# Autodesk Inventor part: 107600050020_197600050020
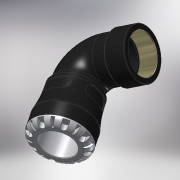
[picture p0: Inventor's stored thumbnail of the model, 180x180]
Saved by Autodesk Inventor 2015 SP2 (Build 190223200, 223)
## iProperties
Created: 2016-12
Part Number: 107600050020_197600050020
Material: PVC-Piping
Description: PLASSON 90° ELBOW WITH FEMALE INTEGRAL BRASS 50X2" SERIES 1
Document SubType Name: Modeling
Designer: KIM
Mass: 664.223 g
Surface Area: 733.008 cm^2
Volume: 474.445 cm^3
Density: 1.4 g/cm^3
Appearance: Black Cast
Author: KIM
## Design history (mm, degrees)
derived "1076.ipt"
feature "Solid1::1076.ipt"
tag "TaggingFeature1"
body "Solid1"
other parameters: "d1" = 33.18, "d3" = 62.5, "d4" = 85, "d8" = 74.8, "d13" = 9, "d14" = 9, "d15" = 0, "d17" = 360 deg, "d19" = 8 deg, "d20" = 1, "d21" = 1, "d22" = 8 deg, "d24" = 0, "d26" = 360 deg, "d33" = 8.5, "d51" = 0.85, "d54" = 17.5, "d55" = 11, "d57" = 17.64, "d58" = 0, "d74" = 0, "d78" = 79, "d82" = 1, "d115" = 360 deg, "d207" = 90 deg, "d228" = 14.875, "d248" = 4.74, "d270" = 122, "d279" = 84, "d281" = 8.4984, "d294" = 56.656, "d295" = 26, "d296" = 28.6, "d297" = 50.9904, "d299" = 66.28752, "d300" = 50.9904, "d301" = 0, "d302" = 0, "d306" = 3.68264, "d309" = 79.79, "d310" = 4.25624, "d312" = 15 deg, "d313" = 0.68, "d314" = 7.584, "d315" = 0.425, "E_" = 85, "l_" = 79, "A_" = 122, "A_1" = 84, "l_2" = 26, "Rp_" = 56.656, "d9" = 11.25, "d11" = 85, "d12" = 62.5, "d298" = 73.6528
